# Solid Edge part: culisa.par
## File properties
Author: user
Template: Normal.par
Last saved by: user
Revision: 4
Application: Solid Edge
Density: 7800.000 kg/m^3
Accuracy: 0.010
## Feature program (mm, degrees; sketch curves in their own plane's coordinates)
sketch for "unnamed Protrusion 1" #1 plane through (0, 0, 0) normal (1, 0, 0) x-axis (0, 1, 0)
  line (5, 5) -> (-5, 5)
  line (-5, 5) -> (-5, -5)
  line (-5, -5) -> (5, -5)
  line (5, -5) -> (5, 5)
sketch for "unnamed Protrusion 1" #2 plane through (0, 0, 0) normal (1, 0, 0) x-axis (0, 1, 0)
  line (-6, -6) -> (6, -6)
  line (6, -6) -> (6, 6)
  line (6, 6) -> (-6, 6)
  line (-6, 6) -> (-6, -6)
extrude "unnamed Protrusion 1" add finite 12 symmetric
sketch for "ExtrudedProtrusion_2" plane through (0, -6, 0) normal (0, -1, 0) x-axis (1, 0, 0)
  circle centre (0, 0) radius 1.5
extrude "ExtrudedProtrusion_2" add finite 6 along +normal
sketch for "ExtrudedProtrusion_3" plane through (0, 0, 6) normal (0, 0, 1) x-axis (1, 0, 0)
  circle centre (0, 0) radius 2
extrude "ExtrudedProtrusion_3" add finite 6 along +normal
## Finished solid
Body 1: solid body, 14 faces, 28 edges, 16 vertices.
  Faces by surface: plane 12, cylinder 2
  Edges by curve: line 24, circle 4
Bounding box of the edges (mm): 12.000 x 18.000 x 18.000, from (-6, -12, -6) to (6, 6, 12).
Cylindrical faces by radius (mm): R1.5 x1, R2 x1
Planar faces by outward normal: +x 1, +y 2, +z 3, -x 1, -y 3, -z 2
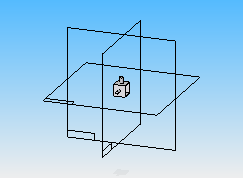
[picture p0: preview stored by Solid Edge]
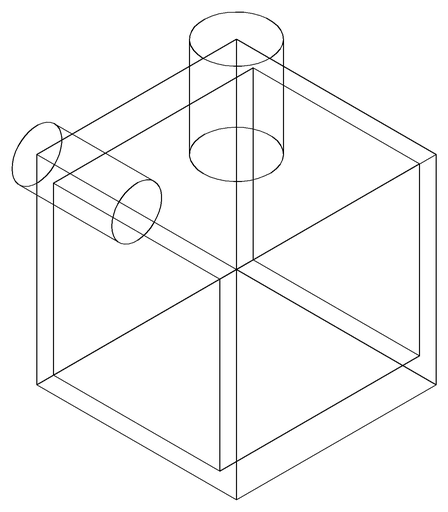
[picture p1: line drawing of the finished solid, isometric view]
